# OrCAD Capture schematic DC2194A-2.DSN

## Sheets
1 LTM4642_SHT2: size Custom; title: HIGH DENSITY, DUAL 4A  STEP-DOWN; rev: 2; company: TM
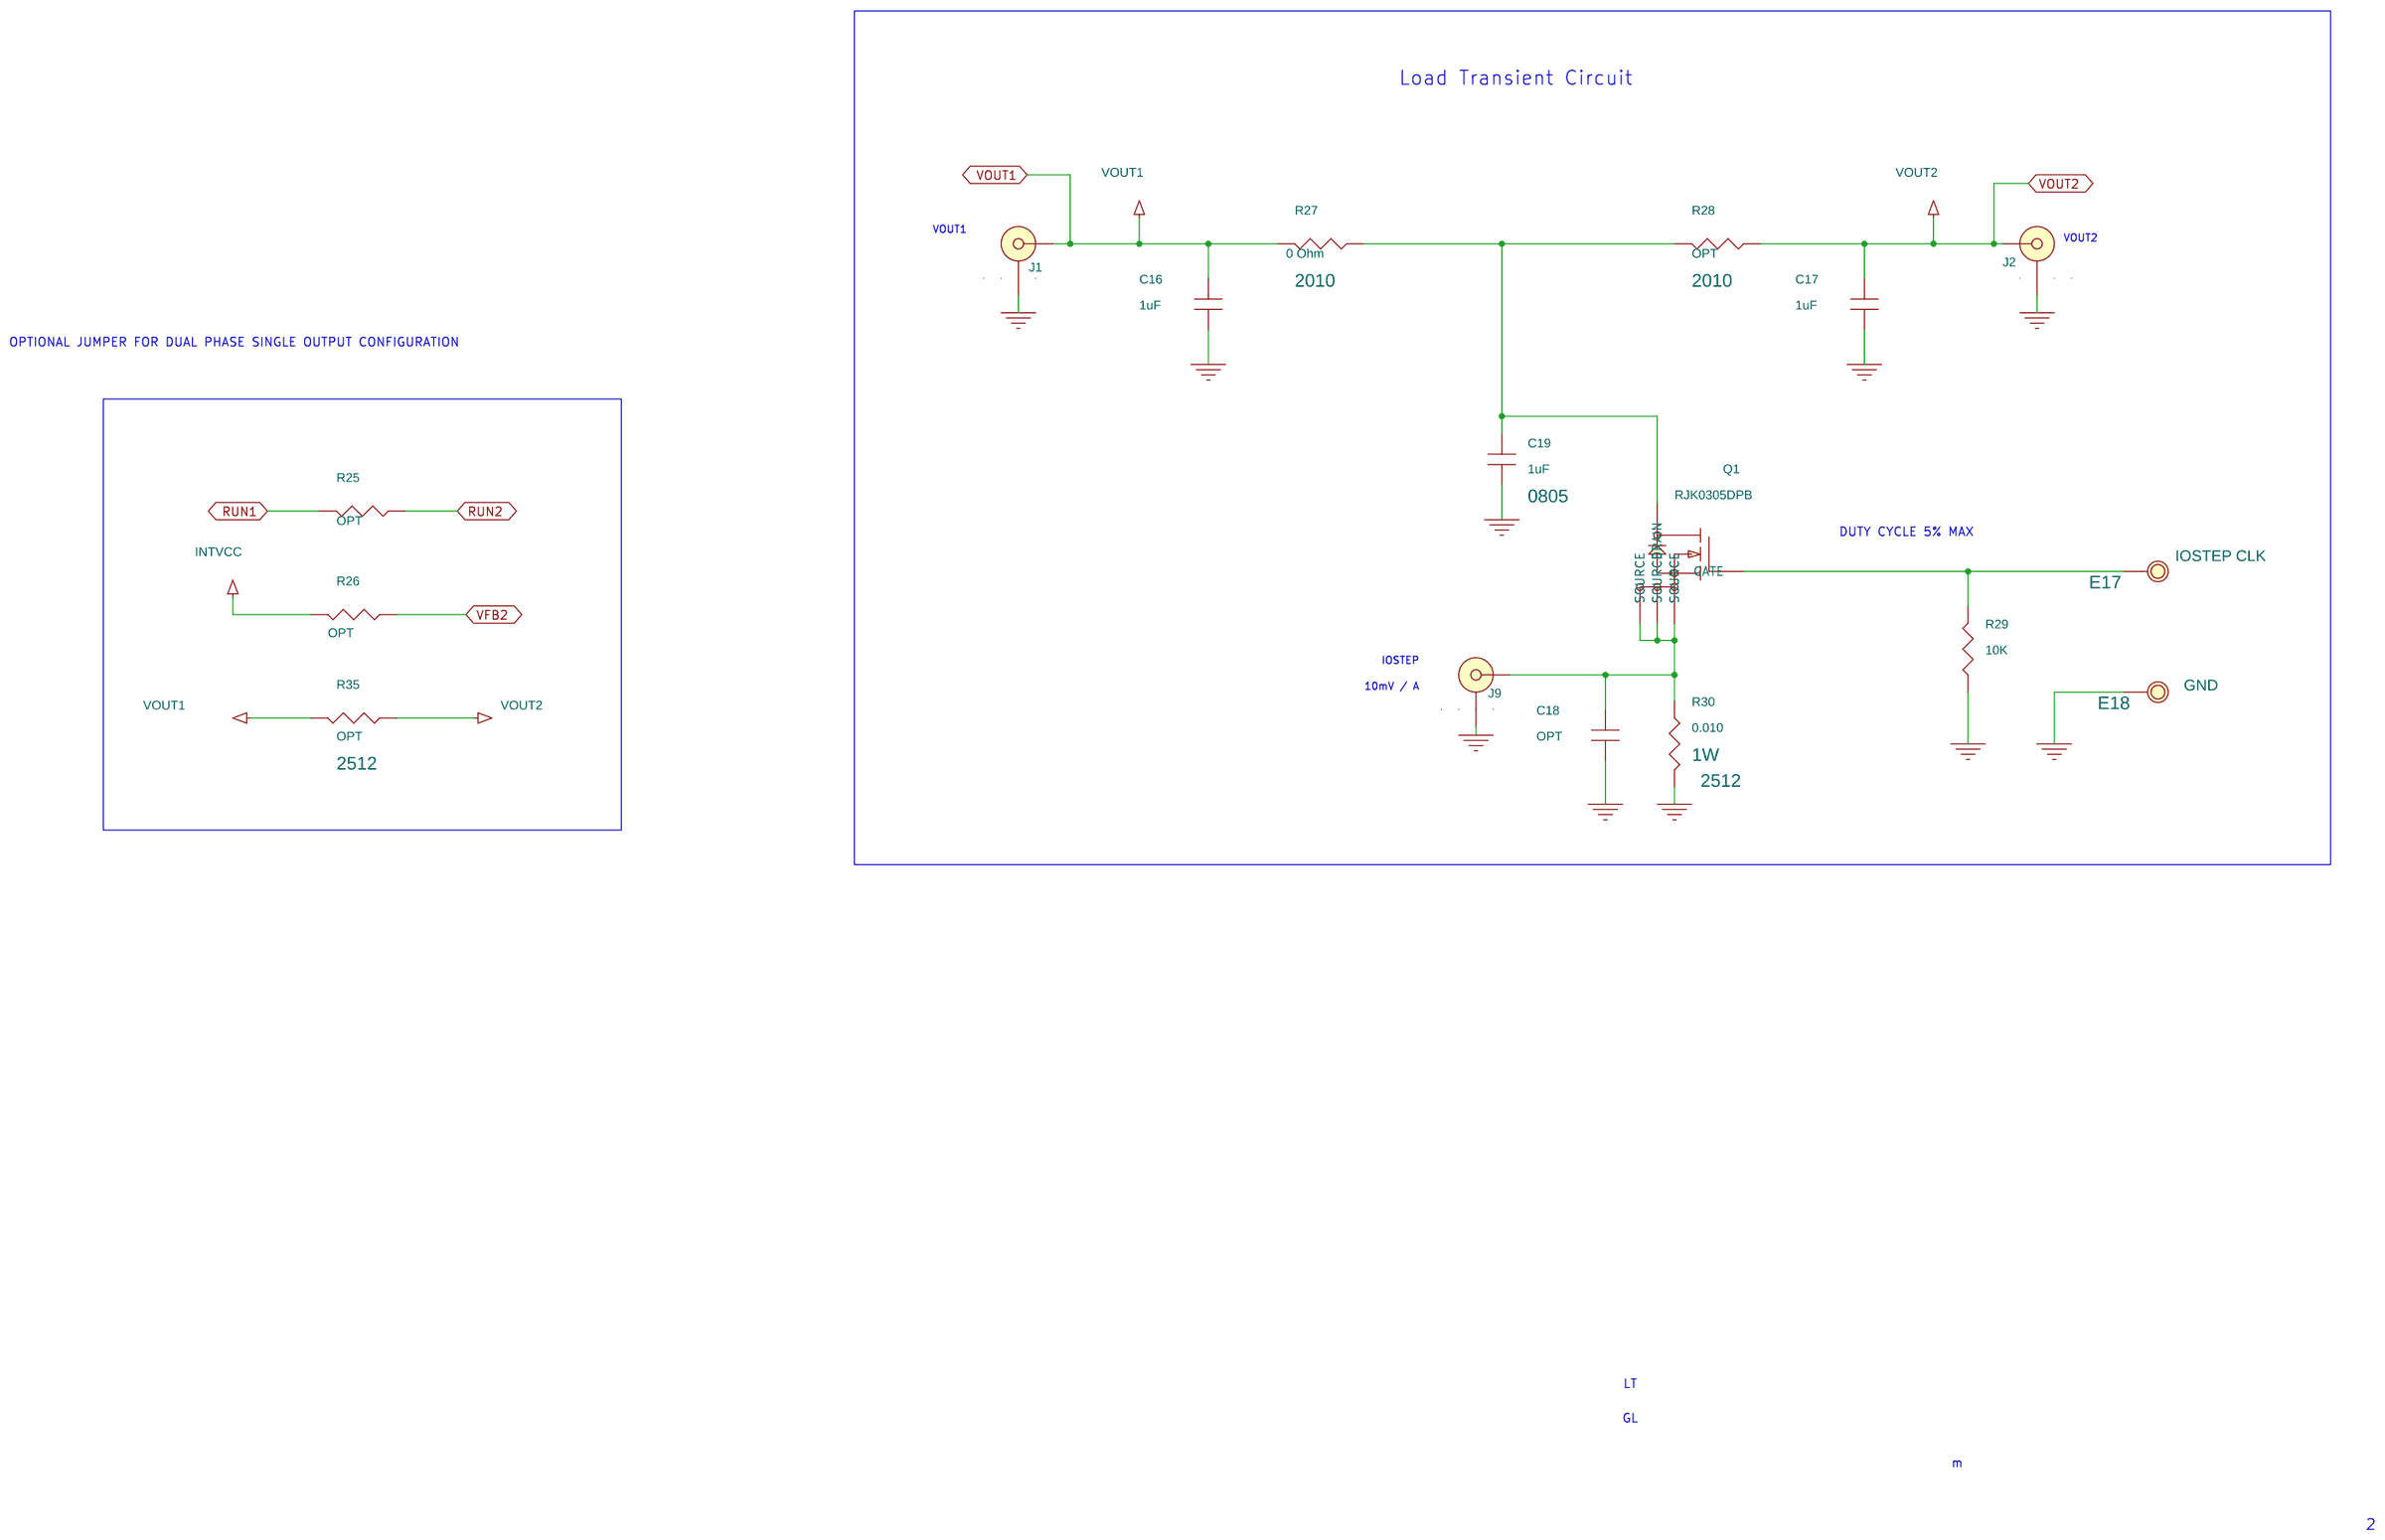
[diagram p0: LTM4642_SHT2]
2 LTM4642_SHT1: size Custom
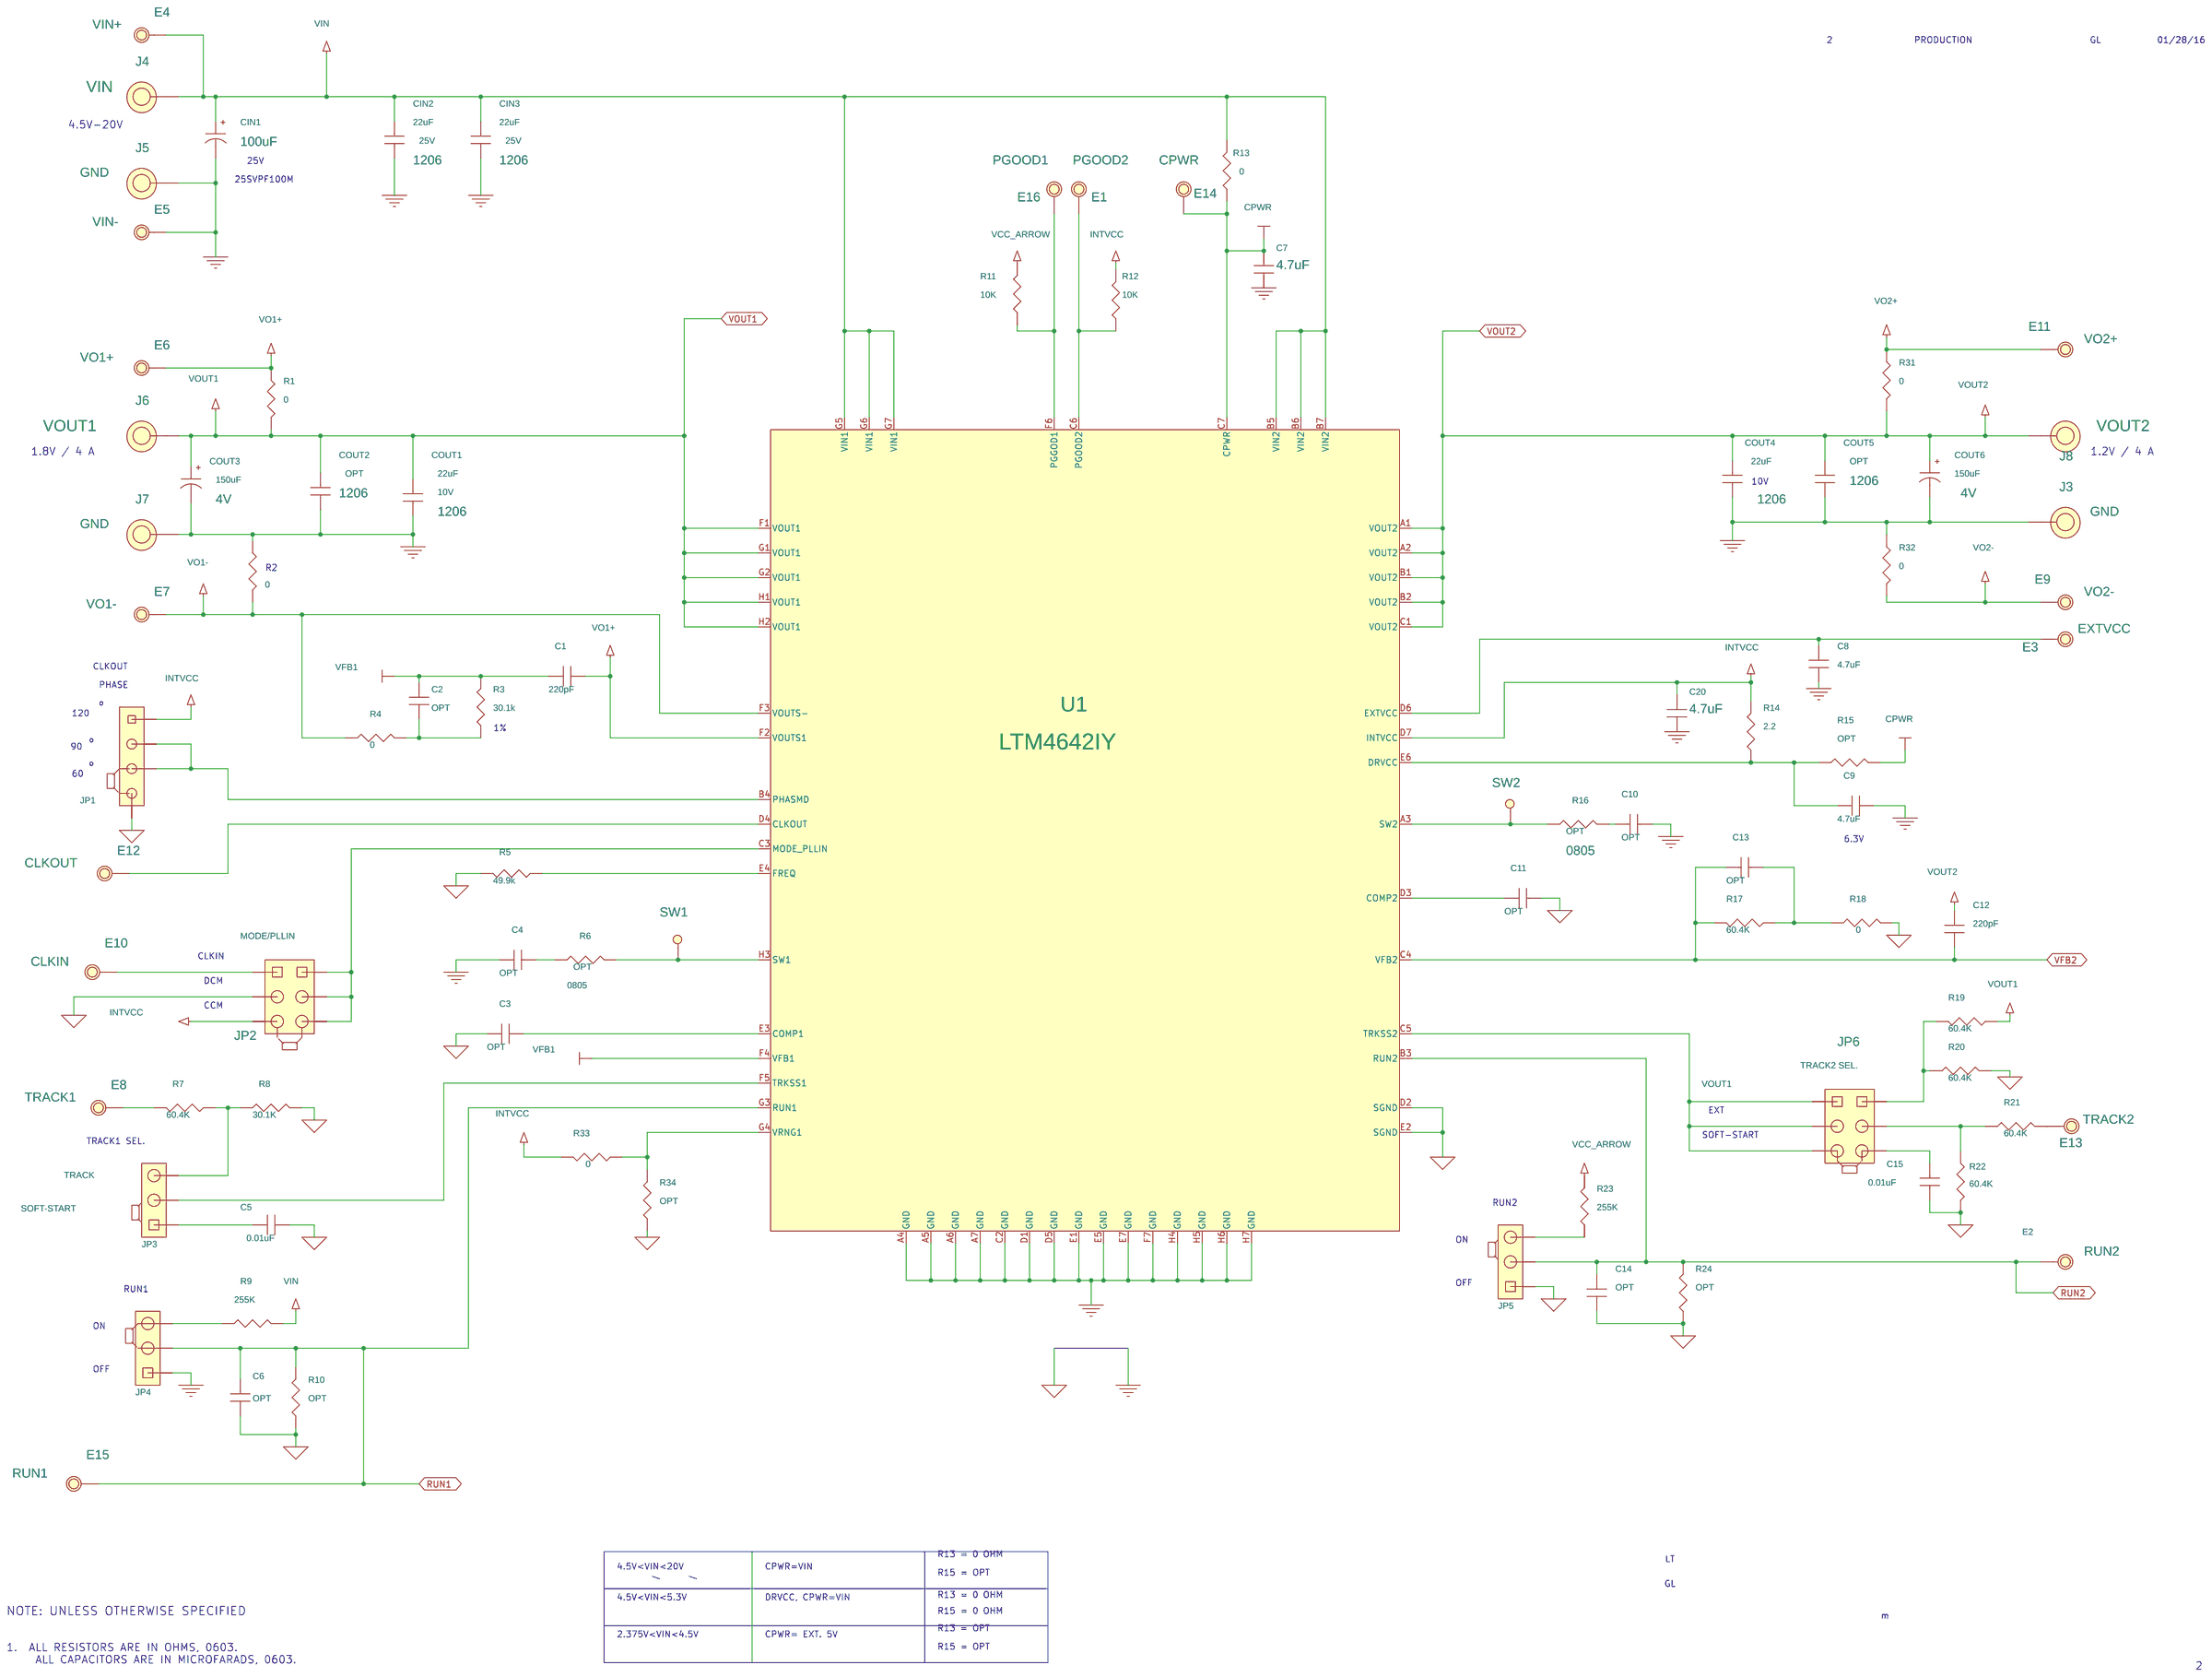
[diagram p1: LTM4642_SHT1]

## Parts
sheet LTM4642_SHT1
C1  220pF  [0603]
C2  OPT  [0603]
C3  OPT  [0603]
C4  OPT  [0603]
C5  0.01uF  [0603]
C6  OPT  [0603]
C7  4.7uF  [0603]
C8  4.7uF  [0603]
C9  4.7uF  [0603]
C10  OPT  [0603]
C11  OPT  [0603]
C12  220pF  [0603]
C13  OPT  [0603]
C14  OPT  [0603]
C15  0.01uF  [0603]
C20  4.7uF  [0603]
CIN1  100uF  [C-SVPF-E7]
CIN2  22uF  [1206]
CIN3  22uF  [1206]
COUT1  22uF  [1206]
COUT2  OPT  [1206]
COUT3  150uF  [SANYO-D4D]
COUT4  22uF  [1206]
COUT5  OPT  [1206]
COUT6  150uF  [SANYO-D4D]
E1  PGOOD2  [MM/2501]
E2  RUN2  [MM/2501]
E3  EXTVCC  [MM/2501]
E4  VIN+  [MM/2501]
E5  VIN-  [MM/2501]
E6  VO1+  [MM/2501]
E7  VO1-  [MM/2501]
E8  TRACK1  [MM/2501]
E9  VO2-  [MM/2501]
E10  CLKIN  [MM/2501]
E11  VO2+  [MM/2501]
E12  CLKOUT  [MM/2501]
E13  TRACK2  [MM/2501]
E14  CPWR  [MM/2501]
E15  RUN1  [MM/2501]
E16  PGOOD1  [MM/2501]
J3  GND  [KEY-575-4]
J4  VIN  [KEY-575-4]
J5  GND  [KEY-575-4]
J6  VOUT1  [KEY-575-4]
J7  GND  [KEY-575-4]
J8  VOUT2  [KEY-575-4]
JP1  4 Pins 2mm Ctrs.  [jumper4pin-79mil]
JP2  3 Pins 2mm Ctrs.  [HD2X3-079]
JP3  3 Pins 2mm Ctrs.  [commcon2802s03g2]
JP4  3 Pins 2mm Ctrs.  [commcon2802s03g2]
JP5  3 Pins 2mm Ctrs.  [commcon2802s03g2]
JP6  3 Pins 2mm Ctrs.  [HD2X3-079]
R1  0  [0603]
R2  0  [0603]
R3  30.1k  [0603]
R4  0  [0603]
R5  49.9k  [0603]
R6  OPT  [0805]
R7  60.4K  [0603]
R8  30.1K  [0603]
R9  255K  [0603]
R10  OPT  [0603]
R11  10K  [0603]
R12  10K  [0603]
R13  0  [0603]
R14  2.2  [0603]
R15  OPT  [0603]
R16  OPT  [0805]
R17  60.4K  [0603]
R18  0  [0603]
R19  60.4K  [0603]
R20  60.4K  [0603]
R21  60.4K  [0603]
R22  60.4K  [0603]
R23  255K  [0603]
R24  OPT  [0603]
R31  0  [0603]
R32  0  [0603]
R33  0  [0603]
R34  OPT  [0603]
SW1  Vin  [SM/TP]
SW2  Vin  [SM/TP]
U1  LTM4642IY  [BGA56-11.25X9X4.92]
XJP5  2mm Ctrs.
XJP6  2mm Ctrs.
XJP8  2mm Ctrs.
XJP9  2mm Ctrs.
XJP10  2mm Ctrs.
XJP11  2mm Ctrs.
sheet LTM4642_SHT2
C16  1uF  [0603]
C17  1uF  [0603]
C18  OPT  [0603]
C19  1uF  [0805]
E17  IOSTEP CLK  [MM/2501]
E18  GND  [MM/2501]
J1  CON-SMA-EDGE  [BNC5]
J2  CON-SMA-EDGE  [BNC5]
J9  CON-SMA-EDGE  [BNC5]
Q1  RJK0305DPB  [LFPAK]
R25  OPT  [0603]
R26  OPT  [0603]
R27  0 Ohm  [2010]
R28  OPT  [2010]
R29  10K  [0603]
R30  0.010  [2512]
R35  OPT  [2512]

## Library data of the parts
C1-C4 C8-C13 = CAP1206: 1ST PART FIELD: 6.3V; 2ND PART FIELD: 0805-1206
C5-C7 C14 C15 C20 COUT4 = CAP1206: 1ST PART FIELD: 25V; 2ND PART FIELD: 0805-1206
CIN1 = CAP-SVPA-E7: 1ST PART FIELD: 25V
CIN2 CIN3 = CAP1210: 1ST PART FIELD: 25V; 2ND PART FIELD: 1210-3743
COUT1 = CAP1210: 1ST PART FIELD: 10V; 2ND PART FIELD: 1210-3743
COUT2 COUT5 = CAP1206: 1ST PART FIELD: 6.3V; 2ND PART FIELD: 0805-1206; VOLTAGE: 6.3V
COUT3 COUT6 = CAP-SVPA-E7: 1ST PART FIELD: 4V; VOLTAGE: 4V
E1-E18 = MillMax-2501
J3-J8 = KEY-575--4_1
JP1 = Commcon2802s03g2_5: 11th Part Field: OFF; 12th Part Field: RUN; 9th Part Field: ON
JP2 = Commcon2802s03g2_4: 11th Part Field: VOUT1; 12th Part Field: MODE/PLLIN; 9th Part Field: ON
JP3-JP5 = Commcon2802s03g2_7: 11th Part Field: SOFT-START; 12th Part Field: TRACK; 9th Part Field: ON
JP6 = Commcon2802s03g2_4: 11th Part Field: VOUT1; 12th Part Field: TRACK2 SEL.; 9th Part Field: ON
R1-R26 R29 R31-R35 = AAC-0603
SW1 SW2 = E_3
U1 = LTM4642EY_2
XJP5 XJP6 XJP8-XJP11 = CommconCCIJ2MM-138G
C16-C19 = CAP0402
J1 J2 J9 = CON-SMA-EDGE_0
Q1 = 2N7000_4
R27 R28 = AAC-0603: 1ST PART FIELD: 0.5W
R30 = AAC-0603: 1ST PART FIELD: 1W

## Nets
GND: C4.2 C7.2 C8.2 C9.1 C10.1 C16.2 C17.2 C18.2 C19.2 C20.2 CIN1.2 CIN2.2 CIN3.2 COUT1.2 COUT2.2 COUT3.2 COUT4.2 COUT5.2 COUT6.2 E5.1 E18.1 J1.2(GND) J1.3 J1.4(GND) J1.5(GND) J2.2(GND) J2.3 J2.4(GND) J2.5(GND) J3.1 J5.1 J7.1 J9.2(GND) J9.3 J9.4(GND) J9.5(GND) JP4.1 R2.1 R29.1 R30.2 R32.1 U1.A4(GND) U1.A5(GND) U1.A6(GND) U1.A7(GND) U1.C2(GND) U1.D1(GND) U1.D5(GND) U1.E1(GND) U1.E5(GND) U1.E7(GND) U1.F7(GND) U1.H4(GND) U1.H5(GND) U1.H6(GND) U1.H7(GND)
GND_SIGNAL: C3.2 C5.2 C6.2 C11.2 C14.2 C15.2 JP1.4 JP2.3 JP5.1 R5.2 R8.2 R10.1 R18.2 R20.2 R22.2 R24.1 R34.1 U1.D2(SGND) U1.E2(SGND)
VIN: CIN1.1 CIN2.1 CIN3.1 E4.1 J4.1 R9.2 R13.2 R23.2 U1.B5(VIN2) U1.B6(VIN2) U1.B7(VIN2) U1.G5(VIN1) U1.G6(VIN1) U1.G7(VIN1)
CPWR: C7.1 E14.1 R13.1 R15.2 U1.C7(CPWR)
INTVCC: C20.1 JP1.1 JP2.5 R11.2 R12.2 R14.2 R26.2 R33.2 U1.D7(INTVCC)
RUN1: C6.1 E15.1 JP4.2 R10.2 R25.2 U1.G3(RUN1)
RUN2: C14.1 E2.1 JP5.2 R24.2 R25.1 U1.B3(RUN2)
VFB1: C1.2 C2.1 R3.2 U1.F4(VFB1)
VFB2: C12.2 C13.1 R17.2 R26.1 U1.C4(VFB2)
VO1+: C1.1 E6.1 R1.1 U1.F2(VOUTS1)
VO1-: E7.1 R2.2 R4.1 U1.F3(VOUTS-)
VO2+: E11.1 R31.1
VO2-: E9.1 R32.2
VOUT1: C16.1 COUT1.1 COUT2.1 COUT3.1 J1.1 J6.1 R1.2 R19.1 R27.2 R35.2 U1.F1(VOUT1) U1.G1(VOUT1) U1.G2(VOUT1) U1.H1(VOUT1) U1.H2(VOUT1)
VOUT2: C12.1 C17.1 COUT4.1 COUT5.1 COUT6.1 J2.1 J8.1 R28.1 R31.2 R35.1 U1.A1(VOUT2) U1.A2(VOUT2) U1.B1(VOUT2) U1.B2(VOUT2) U1.C1(VOUT2)
N1254513: C19.1 Q1.5(DRAIN) R27.1 R28.2
N1255019: E17.1 Q1.4(GATE) R29.2
N16917773: E1.1 R12.1 U1.C6(PGOOD2)
N16952813: JP2.2 JP2.4 JP2.6 U1.C3(MODE_PLLIN)
N17076771: E16.1 R11.1 U1.F6(PGGOD1)
N17260840: C8.1 E3.1 U1.D6(EXTVCC)
N17528848: JP3.3 R7.1 R8.1
N17528892: E8.1 R7.2
N17577687: C9.2 R14.1 R15.1 U1.E6(DRVCC)
N17693074: JP3.2 U1.F5(TRKSS1)
N17955185: E10.1 JP2.1
N18142620: JP6.4 R21.1 R22.1
N18142640: JP6.2 R19.2 R20.1
N18142650: C15.1 JP6.6
N18142679: JP6.1 JP6.3 JP6.5 U1.C5(TRKSS2)
N18346237: JP5.3 R23.1
N18420442: R6.2 SW1.1(A) U1.H3(SW1)
N18582945: C10.2 R16.2
N18600186: C4.1 R6.1
N18861739: C3.1 U1.E3(COMP1)
N19000929: C5.1 JP3.1
N19032876: E12.1 U1.D4(CLKOUT)
N19039691: R5.1 U1.E4(FREQ)
N19097726: JP1.2 JP1.3 U1.B4(PHASMD)
N19134194: C2.2 R3.1 R4.2
N19224101: C11.1 U1.D3(COMP2)
N19261744: C13.2 R17.1 R18.1
N19349901: R16.1 SW2.1(A) U1.A3(SW2)
N19371027: JP4.3 R9.1
N19514196: C18.1 J9.1 Q1.1(SOURCE) Q1.2(SOURCE) Q1.3(SOURCE) R30.1
N19628279: R33.1 R34.2 U1.G4(VRNG1)
N19682710: E13.1 R21.2

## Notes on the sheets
sheet 1
- Load Transient Circuit
- VOUT1
- VOUT2
- OPTIONAL JUMPER FOR DUAL PHASE SINGLE OUTPUT CONFIGURATION
- DUTY CYCLE 5% MAX
- IOSTEP
- 10mV / A
- LT
- GL
- m
- 2
sheet 2
- 2
- PRODUCTION
- GL
- 01/28/16
- 4.5V-20V
- 25V
- 25SVPF100M
- 1.8V / 4 A
- 1.2V / 4 A
- 10V
- R2
- CLKOUT
- PHASE
- o
- 120
- 1%
- 90
- o
- o
- 60
- 6.3V
- CLKIN
- DCM
- CCM
- EXT
- TRACK1 SEL.
- SOFT-START
- RUN2
- ON
- OFF
- RUN1
- ON
- OFF
- R13 = 0 OHM
- LT
- 4.5V<VIN<20V
- CPWR=VIN
- R15 = OPT
- GL
- 4.5V<VIN<5.3V
- DRVCC, CPWR=VIN
- R13 = 0 OHM
- NOTE: UNLESS OTHERWISE SPECIFIED
- R15 = 0 OHM
- m
- 2.375V<VIN<4.5V
- CPWR= EXT. 5V
- R13 = OPT
- 1.  ALL RESISTORS ARE IN OHMS, 0603.
       ALL CAPACITORS ARE IN MICROFARADS, 0603.
- R15 = OPT
- 2
